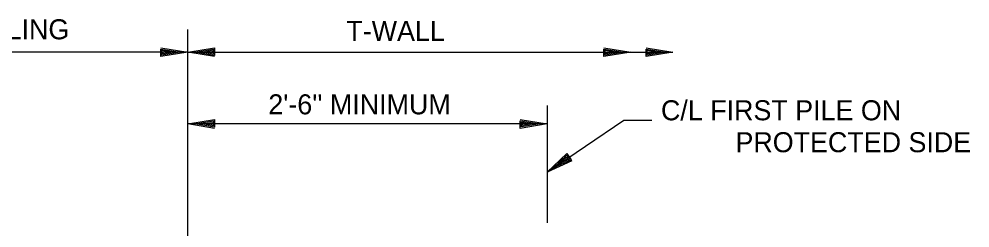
# Model space of a CAD drawing. Extents: x 22369.6 to 22428.3, y 22369.6 to 22415.
# Drawn here: x 22380.52 to 22389.31, y 22383.87 to 22385.81 of the extents above; entities that cross this region are included whole.
import ezdxf

# ---------------------------------------------------------------- set-up
doc = ezdxf.new("R2010")
doc.units = 0
doc.layers.add('Level 1', color=7, linetype='Continuous')
doc.layers.add('Level 4', color=7, linetype='Continuous')

msp = doc.modelspace()

# ---------------------------------------------------------------- linework, layer by layer
at = {"layer": 'Level 1'}
for p, q in [((22382.0776, 22382.2596), (22382.0776, 22385.7117)), ((22385.9275, 22385.5433), (22385.9275, 22385.5433)), ((22385.9275, 22385.5313), (22385.9275, 22385.5313)), ((22382.0776, 22385.5019), (22376.6517, 22385.5019)), ((22382.0082, 22385.5019), (22382.0082, 22385.5019)), ((22382.0776, 22385.5019), (22386.5662, 22385.5019)), ((22382.0776, 22385.5019), (22382.0776, 22385.5019)), ((22382.0776, 22385.5019), (22382.0776, 22385.5019)), ((22382.1466, 22385.5019), (22382.1466, 22385.5019)), ((22385.9275, 22385.4606), (22385.9275, 22385.4606)), ((22385.9382, 22385.5193), (22385.9382, 22385.5193)), ((22385.9382, 22385.4739), (22385.9382, 22385.4739)), ((22385.9489, 22385.5059), (22385.9489, 22385.5059)), ((22385.9489, 22385.4873), (22385.9489, 22385.4873)), ((22385.9715, 22385.5019), (22385.9715, 22385.5019)), ((22386.4969, 22385.5019), (22386.4969, 22385.5019)), ((22386.5662, 22385.5019), (22386.5662, 22385.5019)), ((22385.4026, 22385.0072), (22385.4026, 22383.922)), ((22385.4026, 22384.8369), (22382.0776, 22384.8369)), ((22382.0776, 22384.8369), (22382.0776, 22384.8369)), ((22382.1467, 22384.8369), (22382.1467, 22384.8369)), ((22385.3334, 22384.8369), (22385.3334, 22384.8369)), ((22385.4026, 22384.3906), (22386.1107, 22384.8708)), ((22385.4026, 22384.8369), (22385.4026, 22384.8369)), ((22386.1107, 22384.8708), (22386.37, 22384.8708)), ((22385.4026, 22384.3906), (22385.4026, 22384.3906)), ((22385.4598, 22384.4294), (22385.4598, 22384.4294))]:
    msp.add_line(p, q, dxfattribs=at)
for points in [[(22381.8282, 22385.5433), (22382.0776, 22385.5019), (22381.8282, 22385.4606), (22381.8282, 22385.5313), (22382.0082, 22385.5019), (22381.8389, 22385.4739), (22381.8389, 22385.5193), (22381.9416, 22385.5019), (22381.8496, 22385.4873), (22381.8496, 22385.5059), (22381.8722, 22385.5019)], [(22382.3257, 22385.4608), (22382.0776, 22385.5019), (22382.3257, 22385.5431), (22382.3257, 22385.4728), (22382.1466, 22385.5019), (22382.3151, 22385.5298), (22382.3151, 22385.4847), (22382.2129, 22385.5019), (22382.3044, 22385.5166), (22382.3044, 22385.498), (22382.2819, 22385.5019)], [(22385.9275, 22385.5433), (22386.1769, 22385.5019), (22385.9275, 22385.4606), (22385.9275, 22385.5313), (22386.1075, 22385.5019), (22385.9382, 22385.4739), (22385.9382, 22385.5193), (22386.0409, 22385.5019), (22385.9489, 22385.4873), (22385.9489, 22385.5059), (22385.9715, 22385.5019)], [(22386.3169, 22385.5433), (22386.5662, 22385.5019), (22386.3169, 22385.4606), (22386.3169, 22385.5313), (22386.4969, 22385.5019), (22386.3275, 22385.4739), (22386.3275, 22385.5193), (22386.4302, 22385.5019), (22386.3382, 22385.4873), (22386.3382, 22385.5059), (22386.3609, 22385.5019)], [(22382.3263, 22384.7957), (22382.0776, 22384.8369), (22382.3263, 22384.8782), (22382.3263, 22384.8077), (22382.1467, 22384.8369), (22382.3156, 22384.8649), (22382.3156, 22384.8197), (22382.2132, 22384.8369), (22382.305, 22384.8516), (22382.305, 22384.833), (22382.2824, 22384.8369)], [(22385.1539, 22384.8782), (22385.4026, 22384.8369), (22385.1539, 22384.7957), (22385.1539, 22384.8662), (22385.3334, 22384.8369), (22385.1645, 22384.809), (22385.1645, 22384.8542), (22385.2669, 22384.8369), (22385.1751, 22384.8223), (22385.1751, 22384.8409), (22385.1977, 22384.8369)], [(22385.6316, 22384.496), (22385.4026, 22384.3906), (22385.5853, 22384.5643), (22385.6248, 22384.5059), (22385.4598, 22384.4294), (22385.5839, 22384.5473), (22385.6093, 22384.5099), (22385.5148, 22384.4667), (22385.5826, 22384.5303), (22385.593, 22384.5149), (22385.5721, 22384.5055)]]:
    msp.add_lwpolyline(points, dxfattribs=at)

# ---------------------------------------------------------------- texts
at = {"layer": 'Level 4'}
for s, height, p in [('UNCAPPED SHEET PILING', 0.185698, (22377.822, 22385.6213)), ('T-WALL', 0.1857, (22383.545, 22385.6066)), ("2'-6'' MINIMUM", 0.185698, (22382.823, 22384.926)), ('C/L FIRST PILE ON', 0.185698, (22386.4551, 22384.8708)), ('PROTECTED SIDE', 0.185698, (22387.1441, 22384.5749))]:
    msp.add_text(s, height=height, dxfattribs=at).set_placement(p)

doc.saveas('drawing.dxf')
